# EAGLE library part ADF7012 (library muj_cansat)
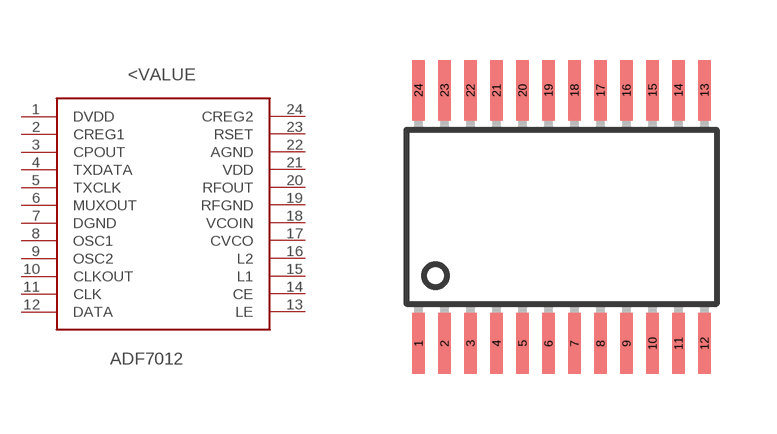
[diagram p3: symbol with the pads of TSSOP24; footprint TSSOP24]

Designator prefix -

## ADF7012  [TSSOP24]
1  DVDD  pwr
2  CREG1
3  CPOUT
4  TXDATA
5  TXCLK
6  MUXOUT
7  DGND  pwr
8  OSC1
9  OSC2
10  CLKOUT
11  CLK
12  DATA
13  LE
14  CE
15  L1
16  L2
17  CVCO
18  VCOIN
19  RFGND
20  RFOUT
21  VDD
22  AGND
23  RSET
24  CREG2

## Footprint TSSOP24 (pad centres in mm)
24-Lead Thin Shrink Small Outline Package TSSOP (RU-24) Source: http://www.analog.com/UploadedFiles/Data_Sheets/39677768AD7714_c.pdf
smd 0.305 x 1.524: 1 -3.575,-3.168; 2 -2.925,-3.168; 3 -2.275,-3.168; 4 -1.625,-3.168; 5 -0.975,-3.168; 6 -0.325,-3.168; 7 0.325,-3.168; 8 0.975,-3.168; 9 1.625,-3.168; 10 2.275,-3.168; 11 2.925,-3.168; 12 3.575,-3.168; 13 3.575,3.168; 14 2.925,3.168; 15 2.275,3.168; 16 1.625,3.168; 17 0.975,3.168; 18 0.325,3.168; 19 -0.325,3.168; 20 -0.975,3.168; 21 -1.625,3.168; 22 -2.275,3.168; 23 -2.925,3.168; 24 -3.575,3.168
